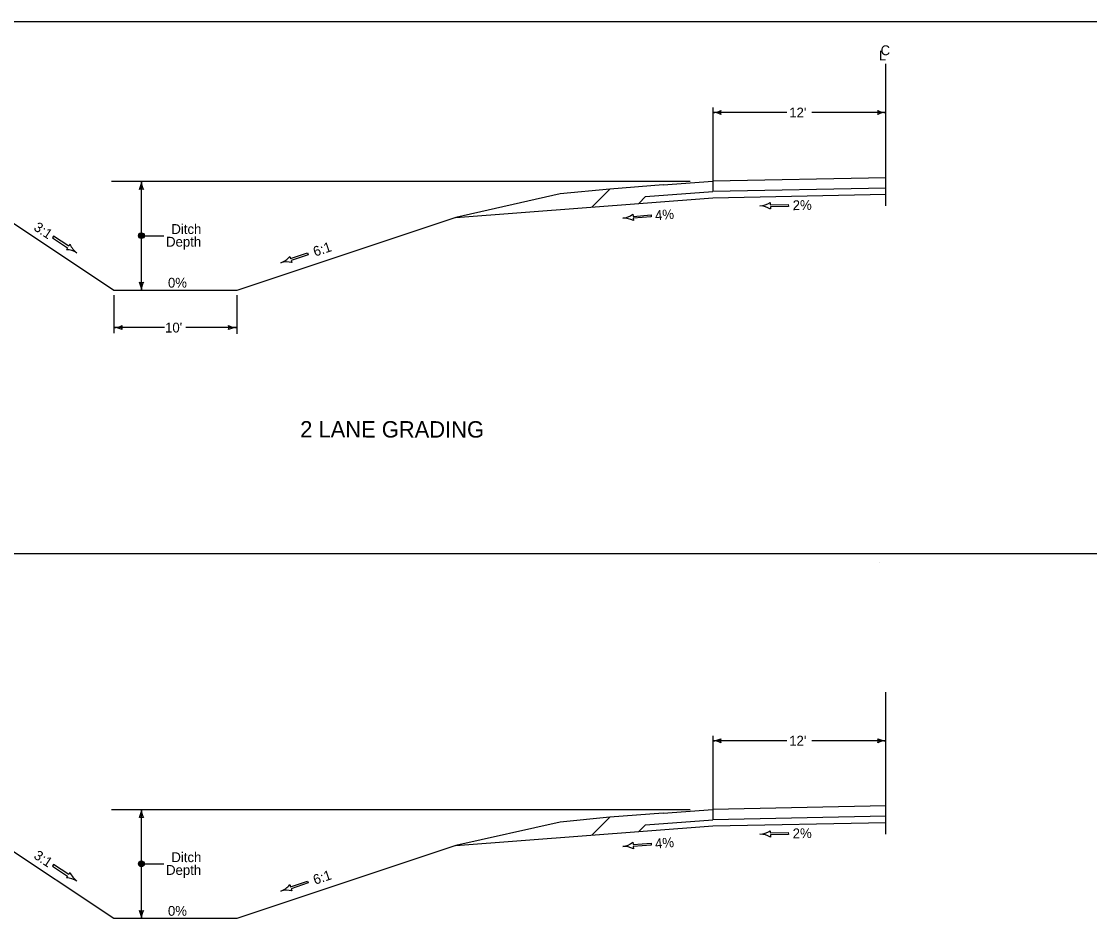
# Model space of a CAD drawing. Extents: x 4574 to 81668, y 5908 to 13780.
# Drawn here: x 10645 to 11949, y 6739 to 7834 of the extents above; entities that cross this region are included whole.
import ezdxf

# ---------------------------------------------------------------- set-up
doc = ezdxf.new("R2010")
doc.units = 0
for name, color, linetype in [('Cell', 7, 'Continuous'), ('Default', 7, 'Continuous'), ('DsnShtRevisedText', 7, 'Continuous'), ('dsnStdBorder', 7, 'Continuous'), ('dsnStdLabel', 7, 'Continuous'), ('dsnTextFinalPlan', 7, 'Continuous'), ('dsnXsSubgrPara', 7, 'Continuous')]:
    doc.layers.add(name, color=color, linetype=linetype)

msp = doc.modelspace()

# ---------------------------------------------------------------- linework, layer by layer
at = {"layer": 'Cell'}
for p, q in [((10757.5, 7505.6), (10577.8, 7625.3)), ((11175, 7594.7), (10907.5, 7505.6)), ((10907.5, 7505.6), (10757.5, 7505.6)), ((10757.5, 6738.7), (10577.8, 6858.5)), ((11175, 6827.9), (10907.5, 6738.7)), ((10907.5, 6738.7), (10757.5, 6738.7))]:
    msp.add_line(p, q, dxfattribs=at)
at = {"layer": 'Default'}
for p, q in [((11700, 7643.1), (11488.5, 7638.9)), ((11362.8, 7629.3), (11302.4, 7623.3)), ((11362.8, 7629.3), (11340.9, 7607.4)), ((11428, 7634.3), (11362.8, 7629.3)), ((11428, 7634.3), (11488.5, 7638.9)), ((11700, 7630.6), (11488.5, 7626.4)), ((11302.4, 7623.3), (11175, 7594.7)), ((11406.6, 7620.1), (11398.3, 7611.8)), ((11406.6, 7620.1), (11488.5, 7626.4)), ((11428, 6867.4), (11488.5, 6872.1)), ((11700, 6876.3), (11488.5, 6872.1)), ((11362.8, 6862.5), (11302.4, 6856.4)), ((11362.8, 6862.5), (11340.9, 6840.6)), ((11428, 6867.4), (11362.8, 6862.5)), ((11406.6, 6853.3), (11488.5, 6859.5)), ((11700, 6863.7), (11488.5, 6859.5)), ((11302.4, 6856.4), (11175, 6827.9)), ((11406.6, 6853.3), (11398.3, 6844.9))]:
    msp.add_line(p, q, dxfattribs=at)
at = {"layer": 'DsnShtRevisedText'}
msp.add_line((11692.5, 7174), (11692.5, 7174), dxfattribs=at)
at = {"layer": 'dsnStdBorder'}
msp.add_lwpolyline([(10147.5, 7834), (13252.5, 7834), (13252.5, 7184), (10147.5, 7184), (10147.5, 7834)], dxfattribs=at)
at = {"layer": 'dsnStdLabel'}
for p, q in [((11546.1, 7608.7), (11546.1, 7608.7)), ((11558.8, 7613), (11558.8, 7610.2)), ((11558.8, 7610.2), (11580.8, 7610.6)), ((11580.9, 7608.2), (11558.9, 7607.8)), ((11558.9, 7607.8), (11558.9, 7605)), ((11580.8, 7610.6), (11580.9, 7608.2)), ((11378.7, 7593.7), (11378.7, 7593.7)), ((11391.1, 7598.7), (11391.3, 7595.9)), ((11391.3, 7595.9), (11413.3, 7597.8)), ((11413.5, 7595.4), (11391.5, 7593.6)), ((11391.5, 7593.6), (11391.8, 7590.8)), ((11413.3, 7597.8), (11413.5, 7595.4)), ((10684.1, 7571.8), (10682.8, 7569.8)), ((10682.8, 7569.8), (10701.1, 7557.6)), ((10702.5, 7559.6), (10684.1, 7571.8)), ((10701.1, 7557.6), (10699.6, 7555.2)), ((10704, 7561.9), (10702.5, 7559.6)), ((10712.4, 7551.5), (10712.4, 7551.5)), ((10973.2, 7544.4), (10994.1, 7551.4)), ((10994.1, 7551.4), (10994.9, 7549.1)), ((10961.5, 7539.3), (10961.5, 7539.3)), ((10972.3, 7547.1), (10973.2, 7544.4)), ((10994.9, 7549.1), (10974, 7542.2)), ((10974, 7542.2), (10974.9, 7539.5)), ((11558.8, 6846.1), (11558.8, 6843.3)), ((11546.1, 6841.9), (11546.1, 6841.9)), ((11558.8, 6843.3), (11580.8, 6843.8)), ((11580.9, 6841.4), (11558.9, 6840.9)), ((11558.9, 6840.9), (11558.9, 6838.1)), ((11580.8, 6843.8), (11580.9, 6841.4)), ((11378.7, 6826.8), (11378.7, 6826.8)), ((11391.1, 6831.9), (11391.3, 6829.1)), ((11391.3, 6829.1), (11413.3, 6831)), ((11413.5, 6828.6), (11391.5, 6826.7)), ((11391.5, 6826.7), (11391.8, 6823.9)), ((11413.3, 6831), (11413.5, 6828.6)), ((10684.1, 6804.9), (10682.8, 6802.9)), ((10682.8, 6802.9), (10701.1, 6790.7)), ((10702.5, 6792.7), (10684.1, 6804.9)), ((10704, 6795), (10702.5, 6792.7)), ((10701.1, 6790.7), (10699.6, 6788.4)), ((10712.4, 6784.6), (10712.4, 6784.6)), ((10973.2, 6777.6), (10994.1, 6784.5)), ((10994.9, 6782.3), (10974, 6775.3)), ((10994.1, 6784.5), (10994.9, 6782.3)), ((10961.5, 6772.4), (10961.5, 6772.4)), ((10972.3, 6780.2), (10973.2, 6777.6)), ((10974, 6775.3), (10974.9, 6772.7))]:
    msp.add_line(p, q, dxfattribs=at)
for centre, start, end in [((11544.5, 7634.5), 273.4978, 303.5278), ((11545.6, 7582.9), 58.7638, 88.7938), ((11375.5, 7619.2), 277.2685, 307.2985), ((11379.9, 7567.9), 62.5344, 92.5645), ((10699, 7529.5), 58.6646, 88.6946), ((10727.6, 7572.3), 203.9305, 233.9606), ((10952.4, 7563.4), 290.787, 320.817), ((10968.6, 7514.5), 76.053, 106.083), ((11544.5, 6867.6), 273.4978, 303.5278), ((11545.6, 6816.1), 58.7638, 88.7938), ((11375.5, 6852.4), 277.2685, 307.2985), ((11379.9, 6801), 62.5344, 92.5645), ((10727.6, 6805.5), 203.9305, 233.9606), ((10699, 6762.6), 58.6646, 88.6946), ((10952.4, 6796.5), 290.787, 320.817), ((10968.6, 6747.6), 76.053, 106.083)]:
    msp.add_arc(centre, 25.8, start, end, dxfattribs=at)
at = {"layer": 'dsnTextFinalPlan'}
for p, q in [((11700, 7608.8), (11700, 7782.2)), ((11488.5, 7728.7), (11488.5, 7626.4)), ((11579.1, 7722.7), (11488.5, 7722.7)), ((11700, 7722.7), (11609.4, 7722.7)), ((10754.8, 7638.9), (11461, 7638.9)), ((10791.2, 7505.6), (10791.2, 7634.9)), ((10791.2, 7572.4), (10818.7, 7572.4)), ((10757.5, 7499.6), (10757.5, 7453.5)), ((10907.5, 7499.6), (10907.5, 7452.7)), ((10819.5, 7460.2), (10757.5, 7460.2)), ((10907.5, 7460.2), (10845.5, 7460.2)), ((11700, 6842), (11700, 7015.3)), ((11488.5, 6961.9), (11488.5, 6859.5)), ((11579.1, 6955.9), (11488.5, 6955.9)), ((11700, 6955.9), (11609.4, 6955.9)), ((10754.8, 6872.1), (11461, 6872.1)), ((10791.2, 6738.7), (10791.2, 6868.1)), ((10791.2, 6805.5), (10818.7, 6805.5))]:
    msp.add_line(p, q, dxfattribs=at)
for points in [[(10791.5, 7569.2), (10790.3, 7569.7), (10788.5, 7570.3), (10788.1, 7572.1), (10788.4, 7573.8), (10789.6, 7575.3), (10791.3, 7575.1), (10793.2, 7574.9), (10794, 7573.4), (10794.2, 7571.8), (10793.1, 7569.8), (10791.8, 7569.7), (10789.9, 7570.1), (10788.4, 7571.3), (10788.5, 7573), (10789.6, 7574.4), (10791.3, 7574.6), (10793.1, 7574.2), (10793.4, 7573.2), (10793.8, 7572), (10792.9, 7570.4), (10791.6, 7570.5), (10790.1, 7570.7), (10788.9, 7571.6), (10789.5, 7573.1), (10790.7, 7574), (10792.2, 7574.1), (10792.6, 7573.2), (10793.1, 7572.3), (10792.3, 7571.1), (10791.2, 7570.8), (10790.2, 7571.3), (10790.1, 7572.5), (10790.6, 7573.3), (10791.7, 7573.6), (10792.2, 7573.1), (10792.5, 7572.5), (10791.9, 7571.6), (10791.2, 7571.4), (10790.5, 7571.9), (10790.6, 7572.5), (10791.1, 7572.9), (10791.9, 7572.8), (10791.8, 7572.3), (10791.2, 7572)], [(10791.5, 6802.3), (10790.3, 6802.8), (10788.5, 6803.4), (10788.1, 6805.3), (10788.4, 6806.9), (10789.6, 6808.4), (10791.3, 6808.3), (10793.2, 6808), (10794, 6806.5), (10794.2, 6805), (10793.1, 6803), (10791.8, 6802.8), (10789.9, 6803.3), (10788.4, 6804.4), (10788.5, 6806.2), (10789.6, 6807.6), (10791.3, 6807.8), (10793.1, 6807.4), (10793.4, 6806.4), (10793.8, 6805.1), (10792.9, 6803.6), (10791.6, 6803.6), (10790.1, 6803.9), (10788.9, 6804.7), (10789.5, 6806.3), (10790.7, 6807.2), (10792.2, 6807.2), (10792.6, 6806.4), (10793.1, 6805.4), (10792.3, 6804.2), (10791.2, 6803.9), (10790.2, 6804.5), (10790.1, 6805.6), (10790.6, 6806.4), (10791.7, 6806.7), (10792.2, 6806.3), (10792.5, 6805.7), (10791.9, 6804.7), (10791.2, 6804.6), (10790.5, 6805), (10790.6, 6805.6), (10791.1, 6806), (10791.9, 6806), (10791.8, 6805.5), (10791.2, 6805.2)]]:
    msp.add_lwpolyline(points, dxfattribs=at)
for centre in [(10791.2, 7572.4), (10791.2, 6805.5)]:
    msp.add_circle(centre, 3.5, dxfattribs=at)
for centre, radius, start, end in [((11488.5, 7744), 21.3, 270, 298.0725), ((11488.5, 7701.5), 21.3, 61.9275, 90), ((11506.3, 7722.7), 8.21, 162.2666, 197.7334), ((11682.2, 7722.7), 8.21, 342.2667, 17.7334), ((11700, 7744), 21.3, 241.9275, 270), ((11700, 7701.5), 21.3, 90, 118.0725), ((10770, 7638.9), 21.3, 331.9275, 360), ((10791.2, 7621.1), 8.21, 72.2666, 107.7334), ((10812.5, 7638.9), 21.3, 180, 208.0725), ((10791.2, 7523.4), 8.21, 252.2666, 287.7334), ((10770, 7505.6), 21.3, 360, 28.0725), ((10812.5, 7505.6), 21.3, 151.9275, 180), ((10757.5, 7481.5), 21.3, 270, 298.0725), ((10757.5, 7439), 21.3, 61.9275, 90), ((10775.3, 7460.2), 8.21, 162.2666, 197.7334), ((10889.7, 7460.2), 8.21, 342.2666, 17.7334), ((10907.5, 7481.5), 21.3, 241.9275, 270), ((10907.5, 7439), 21.3, 90, 118.0725), ((11488.5, 6977.1), 21.3, 270, 298.0725), ((11488.5, 6934.6), 21.3, 61.9275, 90), ((11506.3, 6955.9), 8.21, 162.2666, 197.7334), ((11682.2, 6955.9), 8.21, 342.2667, 17.7334), ((11700, 6977.1), 21.3, 241.9275, 270), ((11700, 6934.6), 21.3, 90, 118.0725), ((10770, 6872.1), 21.3, 331.9275, 360), ((10812.5, 6872.1), 21.3, 180, 208.0725), ((10791.2, 6854.2), 8.21, 72.2666, 107.7334), ((10791.2, 6756.5), 8.21, 252.2666, 287.7334), ((10770, 6738.7), 21.3, 360, 28.0725), ((10812.5, 6738.7), 21.3, 151.9275, 180)]:
    msp.add_arc(centre, radius, start, end, dxfattribs=at)
at = {"layer": 'dsnXsSubgrPara'}
for p, q in [((11175, 7594.7), (11488.5, 7618.7)), ((11488.5, 7618.7), (11700, 7622.9)), ((11175, 6827.9), (11488.5, 6851.8)), ((11488.5, 6851.8), (11700, 6856))]:
    msp.add_line(p, q, dxfattribs=at)

# ---------------------------------------------------------------- texts
at = {"layer": 'dsnStdLabel'}
for s, p in [('L', (11691.4, 7786.4)), ('C', (11693.5, 7792.7))]:
    msp.add_text(s, height=12, dxfattribs=at).set_placement(p)
for s, height, rotation, p in [('2%', 12, 1.1458, (11586.3, 7603.5)), ('4%', 12, 4.9165, (11418.6, 7591.1)), ('3:1', 12, 326.3126, (10658.8, 7580)), ('6:1', 12, 18.435, (11003.2, 7546.8)), ('2 LANE GRADING', 20, 359.9583, (10985, 7326.1)), ('2%', 12, 1.1458, (11586.3, 6836.7)), ('4%', 12, 4.9165, (11418.6, 6824.2)), ('3:1', 12, 326.3126, (10658.8, 6813.1)), ('6:1', 12, 18.435, (11003.2, 6780))]:
    msp.add_text(s, height=height, rotation=rotation, dxfattribs=at).set_placement(p)
at = {"layer": 'dsnTextFinalPlan'}
for s, p in [("12'", (11581.9, 7716.7)), ('Ditch', (10827.8, 7574.5)), ('Depth', (10821.3, 7559)), ('0%', (10823.6, 7509)), ("10'", (10820.1, 7454.2)), ("12'", (11581.9, 6949.9)), ('Ditch', (10827.8, 6807.7)), ('Depth', (10821.3, 6792.1)), ('0%', (10823.6, 6742.2))]:
    msp.add_text(s, height=12, dxfattribs=at).set_placement(p)

doc.saveas('drawing.dxf')
